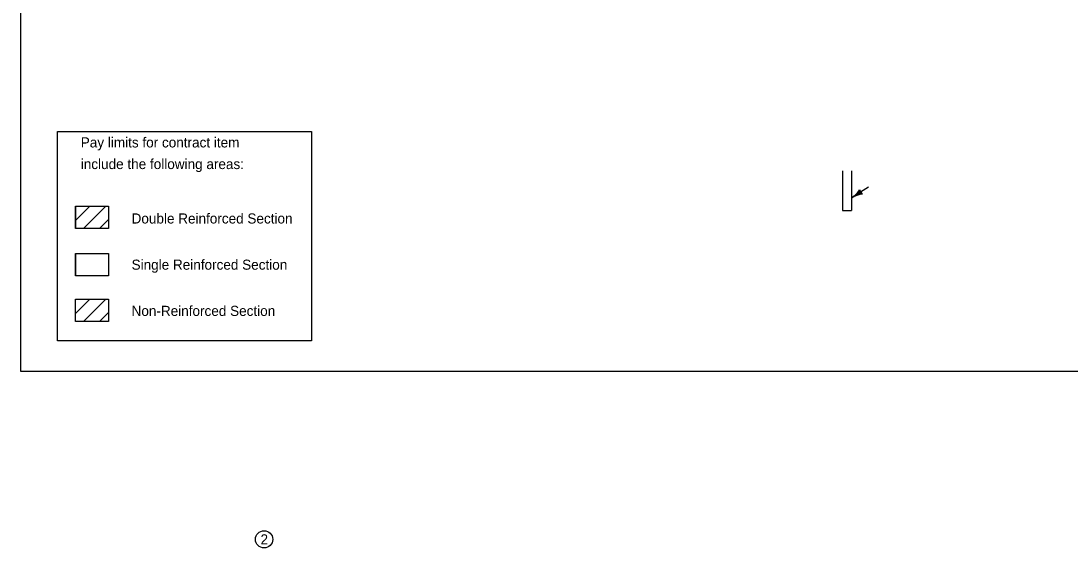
# Model space of a CAD drawing. Extents: x 10045 to 81668, y 6370 to 11018.
# Drawn here: x 13733 to 15638, y 7603 to 8561 of the extents above; entities that cross this region are included whole.
import ezdxf

# ---------------------------------------------------------------- set-up
doc = ezdxf.new("R2010")
doc.units = 0
for name, color, linetype in [('Alignment', 7, 'Continuous'), ('dsnStdLineWork', 7, 'Continuous'), ('Level 5', 7, 'Continuous')]:
    doc.layers.add(name, color=color, linetype=linetype)

msp = doc.modelspace()

# ---------------------------------------------------------------- linework, layer by layer
at = {"layer": 'Alignment'}
for p, q in [((15271.4, 8258.8), (15240.8, 8239.6)), ((13831.6, 8224.3), (13891.3, 8224.3)), ((13831.6, 8183.8), (13831.6, 8224.3)), ((13891.3, 8224.3), (13891.3, 8183.8)), ((13891.3, 8183.8), (13831.6, 8183.8)), ((13831.6, 8138.2), (13891.3, 8138.2)), ((13831.6, 8097.8), (13831.6, 8138.2)), ((13891.3, 8138.2), (13891.3, 8097.8)), ((13891.3, 8097.8), (13831.6, 8097.8))]:
    msp.add_line(p, q, dxfattribs=at)
at = {"layer": 'dsnStdLineWork'}
for p, q in [((15224.4, 8288.9), (15224.4, 8216.4)), ((15240.8, 8288.9), (15240.8, 8216.4)), ((15240.8, 8239.6), (15257.6, 8250.1)), ((13831.6, 8224.3), (13891.3, 8224.3)), ((13831.6, 8224.3), (13831.6, 8183.8)), ((13831.6, 8198.7), (13857.3, 8224.3)), ((13845.9, 8183.8), (13886.4, 8224.3)), ((13891.3, 8224.3), (13891.3, 8183.8)), ((15224.4, 8216.4), (15240.8, 8216.4)), ((13875, 8183.8), (13891.3, 8200.2)), ((13891.3, 8183.8), (13831.6, 8183.8)), ((13831.6, 8138.2), (13891.3, 8138.2)), ((13831.6, 8138.2), (13831.6, 8097.8)), ((13891.3, 8138.2), (13891.3, 8097.8)), ((13891.3, 8097.8), (13831.6, 8097.8)), ((13831.6, 8029.6), (13857.3, 8055.3)), ((13845.9, 8014.8), (13886.4, 8055.3)), ((13875, 8014.8), (13891.3, 8031.2))]:
    msp.add_line(p, q, dxfattribs=at)
for points in [[(13798.9, 8360.3), (14260.1, 8360.3), (14260.1, 7980), (13798.9, 7980)], [(13831.6, 8055.3), (13891.3, 8055.3), (13891.3, 8014.8), (13831.6, 8014.8)]]:
    msp.add_lwpolyline(points, close=True, dxfattribs=at)
msp.add_lwpolyline([(15259.2, 8246.8), (15256.6, 8249.5), (15255.3, 8253.1), (15252.7, 8248.9), (15247.6, 8243.9), (15254.9, 8246.4), (15258.4, 8246.9), (15256, 8249.2), (15255, 8251.3), (15253.3, 8248.6), (15250.5, 8245.7), (15254.7, 8246.9), (15256.9, 8247.4), (15254.9, 8249.9), (15253.1, 8247.3), (15255.4, 8247.9), (15254.8, 8248.9), (15254.1, 8248)], dxfattribs=at)
msp.add_circle((14174.1, 7618.8), 15.7, dxfattribs=at)
for centre, radius, start, end in [((15217.6, 8276.6), 43.7, 302.0841, 330.1566), ((15271.9, 8259.1), 16.9, 194.3508, 229.8175), ((15264.1, 8202.6), 43.7, 94.0116, 122.0841)]:
    msp.add_arc(centre, radius, start, end, dxfattribs=at)
at = {"layer": 'Level 5'}
msp.add_lwpolyline([(13732.5, 9944), (16867.5, 9944), (16867.5, 7924), (13732.5, 7924)], close=True, dxfattribs=at)

# ---------------------------------------------------------------- texts
at = {"layer": 'Alignment'}
for s, height, p in [('Pay limits for contract item', 18.375, (13841.1, 8331.3)), ('include the following areas:', 18.375, (13841.1, 8292)), ('Double Reinforced Section', 18.375, (13933.4, 8193)), ('Single Reinforced Section', 18.375, (13933.4, 8109)), ('Non-Reinforced Section', 18.375, (13933.4, 8025)), ('2', 18.4, (14167.5, 7609.6))]:
    msp.add_text(s, height=height, dxfattribs=at).set_placement(p)

doc.saveas('drawing.dxf')
